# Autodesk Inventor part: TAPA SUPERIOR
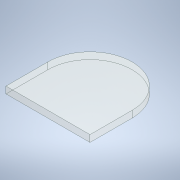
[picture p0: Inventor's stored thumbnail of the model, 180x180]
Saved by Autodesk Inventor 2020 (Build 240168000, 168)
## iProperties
Created: 2022-09
Part Number: TAPA SUPERIOR
Material: Vidrio
Document SubType Name: Modeling
Designer: SEBAS
Density: 2.18 g/cm^3
Appearance: Claro
Author: SEBAS
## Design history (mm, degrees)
sketch "Boceto1"
  geometry: L1 (31, 0)-(31, 31); L2 (-31, 31)-(-31, 0); L3 (31, 31)-(-31, 31); A1 r 31 centre (0, 0) between (-31, 0) and (31, 0); 2 further points
  constraints: 6 end point, 3 vertical alignment, 2 point on circle, 1 centre point, 1 coincident, 1 horizontal alignment, 1 midpoint
  dimensions: "d1" = 31 distance of L1.start L1.end; "d2" = 62 distance between parallel lines of L2 L1; "d5" = 31 radius of A1
extrude "Extrusión1" new body sketch "Boceto1" distance "d3" = 5; taper "d4" = 0 deg
node "Sólido1"
